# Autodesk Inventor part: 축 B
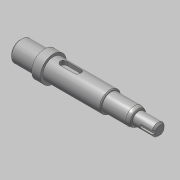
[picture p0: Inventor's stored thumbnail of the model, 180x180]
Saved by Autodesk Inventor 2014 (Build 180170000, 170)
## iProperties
Created: 2020-04
Part Number: 축 B
Material: 강철, 연강
Document SubType Name: Modeling
Designer: mduedu
Density: 7.86 g/cm^3
Appearance: Steel
Mass: 60.8598 g
Surface Area: 31.2859 cm^2
Volume: 7.74298 cm^3
Author: mduedu
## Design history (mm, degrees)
sketch "스케치1"
  geometry: L1 (0, 0)-(14, 0); L2 (14, 0)-(14, 6); L3 (14, 6)-(0, 6); L4 (0, 6)-(0, 0); L5 (14, 0)-(19, 0); L6 (19, 0)-(19, 7.5); L7 (19, 7.5)-(14, 7.5); L8 (14, 7.5)-(14, 0); L9 (19, 0)-(52, 0); L10 (52, 0)-(52, 6); L11 (52, 6)-(19, 6); L12 (19, 6)-(19, 0); L13 (52, 0)-(68, 0); L14 (68, 0)-(68, 5); L15 (68, 5)-(52, 5); L16 (52, 5)-(52, 0); L17 (68, 0)-(80, 0); L18 (80, 0)-(80, 3.5); L19 (80, 3.5)-(68, 3.5); L20 (68, 3.5)-(68, 0)
  constraints: 40 end point, 10 parallel, 5 horizontal, 5 perpendicular
  dimensions: "d0" = 80 distance between parallel lines of L18 L4; "d2" = 14 distance of L2.end L3.end; "d3" = 5 distance of L6.end L7.end; "d5" = 7 diameter of L19 L17; "d6" = 10 diameter of L15 L13; "d7" = 12 diameter of L11 L9; "d8" = 12 diameter of L3 L1; "d9" = 15 diameter of L7 L5; "d35" = 16 distance of L14.end L15.end; "d36" = 52 distance between parallel lines of L10 L4
revolve "회전1" sketch "스케치1" stored, may be unused: angle "d11" = 90 deg
sketch "스케치2"
  geometry: L1 (0, 6)-(0, -6) reference; L2 (0, -6)-(-14, -6) reference; L3 (-14, -6)-(-14, -7.5) reference; L4 (-14, -7.5)-(-19, -7.5) reference; L5 (-19, -7.5)-(-19, -6) reference; L6 (-19, -6)-(-52, -6) reference; L7 (-52, -6)-(-52, -5) reference; L8 (-52, -5)-(-68, -5) reference; L9 (-68, -5)-(-68, -3.5) reference; L10 (-68, -3.5)-(-80, -3.5) reference; L11 (-80, -3.5)-(-80, 3.5) reference; L12 (-80, 3.5)-(-68, 3.5) reference; L13 (-68, 3.5)-(-68, 5) reference; L14 (-68, 5)-(-52, 5) reference; L15 (-52, 5)-(-52, 6) reference; L16 (-52, 6)-(-19, 6) reference; L17 (-19, 6)-(-19, 7.5) reference; L18 (-19, 7.5)-(-14, 7.5) reference; L19 (-14, 7.5)-(-14, 6) reference; L20 (-14, 6)-(0, 6) reference; L21 (-80, 3.5)-(-72, 3.5); L22 (-72, 3.5)-(-72, 2.3); L23 (-72, 2.3)-(-80, 2.3); L24 (-80, 2.3)-(-80, 3.5); 1 further point
  constraints: 8 end point, 2 parallel, 1 horizontal, 1 perpendicular
  dimensions: "d37" = 8 distance of L22.end L23.end; "d38" = 1.2 distance of L21.end L22.end
extrude "돌출1" cut sketch "스케치2" stored distance "d14" = 2; taper "d15" = 0 deg
fillet "모깎기1" dims "d16" = 1
sketch "스케치3"
  geometry: L1 (0, -6)-(0, 6) reference; L2 (0, 6)-(14, 6) reference; L3 (14, 6)-(14, 7.5) reference; L4 (14, 7.5)-(19, 7.5) reference; L5 (19, 7.5)-(19, 6) reference; L6 (19, 6)-(52, 6) reference; L7 (52, 6)-(52, 5) reference; L8 (52, 5)-(68, 5) reference; L9 (68, 5)-(68, 3.5) reference; L10 (68, 3.5)-(80, 3.5) reference; L11 (80, 3.5)-(80, -3.5) reference; L12 (80, -3.5)-(68, -3.5) reference; L13 (68, -3.5)-(68, -5) reference; L14 (68, -5)-(52, -5) reference; L15 (52, -5)-(52, -6) reference; L16 (52, -6)-(19, -6) reference; L17 (19, -6)-(19, -7.5) reference; L18 (19, -7.5)-(14, -7.5) reference; L19 (14, -7.5)-(14, -6) reference; L20 (14, -6)-(0, -6) reference; L21 (23, 6)-(35, 6); L22 (35, 6)-(35, 3.5); L23 (35, 3.5)-(23, 3.5); L24 (23, 3.5)-(23, 6); 1 further point
  constraints: 8 end point, 2 parallel, 1 horizontal, 1 perpendicular, 1 point on line
  dimensions: "d17" = 12 distance of L22.end L23.end; "d18" = 2.5 distance of L21.end L22.end; "d19" = 4 distance from line of L24 L4.end
extrude "돌출2" cut sketch "스케치3" stored distance "d20" = 4; taper "d21" = 0 deg
fillet "모깎기2" dims "d22" = 2
chamfer "모따기1" distance "d23" = 1; stored, may be unused: second distance "d24" = 2, angle "d25" = 45 deg
chamfer "모따기2" distance "d26" = 0.5; stored, may be unused: second distance "d27" = 2, angle "d28" = 45 deg
fillet "모깎기3" dims "d29" = 0.3
chamfer "모따기3" distance "d30" = 1.39; stored, may be unused: second distance "d31" = 2, angle "d32" = 30 deg
fillet "모깎기4" dims "d33" = 4, "d34" = 0.5
node "솔리드1"
node "절단 모서리 투영2"
node "절단 모서리 투영3"
